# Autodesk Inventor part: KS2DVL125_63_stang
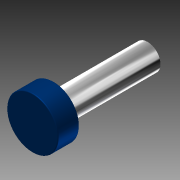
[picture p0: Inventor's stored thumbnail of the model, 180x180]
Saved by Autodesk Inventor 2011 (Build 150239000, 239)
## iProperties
Created: 2010-11
Document SubType Name: Modeling
Designer: TB
Mass: 161.233 g
Surface Area: 236.814 cm^2
Volume: 161.233 cm^3
Density: 1 g/cm^3
Author: TB
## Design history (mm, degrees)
sketch "Sketch2"
  geometry: L1 (-35, -3)-(-35, 3) reference; L2 (-35, -9)-(-35, 9) reference; L3 (-35, 31.5)-(-328, 31.5); L4 (-328, 31.5)-(-328, 0); L5 (-328, 0)-(-35, 0); L6 (-35, 0)-(-35, 31.5); L7 (-328, 31.5)-(-276, 31.5); L8 (-276, 31.5)-(-276, 62.5); L9 (-276, 62.5)-(-328, 62.5); L10 (-328, 62.5)-(-328, 31.5); 1 further point
  constraints: 16 end point, 4 parallel, 2 horizontal, 2 perpendicular, 1 midpoint
  dimensions: "Dia" = 63 diameter of L3 L5; "d3" = 293 distance of L3.start L3.end (computed from Slaglengde, Forlengelse_rør); "StempelDia" = 125 diameter of L9 L5; "StempelLengde" = 52 distance of L8.end L9.end
revolve "Revolution1" sketch "Sketch2" stored, may be unused: angle "d6" = 90 deg
fillet "Fillet1" dims "d7" = 2
sketch "Sketch3"
  geometry: L1 (-328, -60.5)-(-328, 60.5) reference; L2 (-328, 0)-(-328.01, 0); L3 (-328, 0)-(-328, 0.01); A1 r 0.01 centre (-328, 0) between (-328, 0.01) and (-328.01, 0); 1 further point
  constraints: 4 end point, 2 point on circle, 1 centre point, 1 midpoint, 1 perpendicular, 1 point on line
  dimensions: "d8" = 0.01 distance of L2.start L2.end; "d9" = 0.01 distance of L2.start L3.end (= d8); "d10" = 0.01 radius of A1 (= d8)
revolve "Revolution2" sketch "Sketch3" stored, may be unused: angle "d11" = 90 deg
body "Solid1"
node "Projected Loop2"
other parameters: "Forlengelse_rør" = 0
